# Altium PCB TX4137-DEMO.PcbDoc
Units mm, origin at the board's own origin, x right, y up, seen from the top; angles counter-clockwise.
Board outline 10 x 11 mm, 2 copper layers (Top Layer, Bottom Layer); 11 components, 7 nets, 40 pads, 0 vias.
Unrouted connection lines stored in the file: 3.
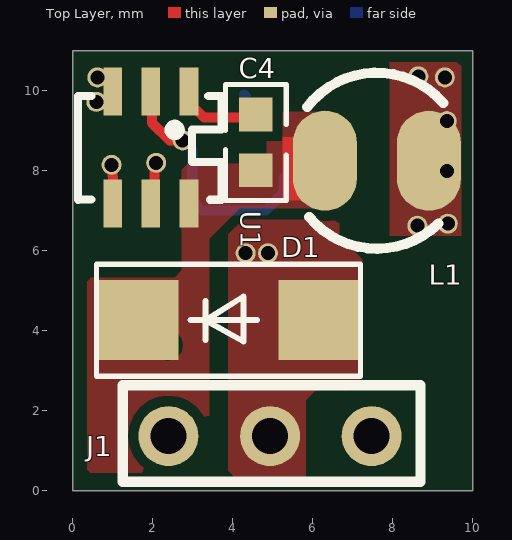
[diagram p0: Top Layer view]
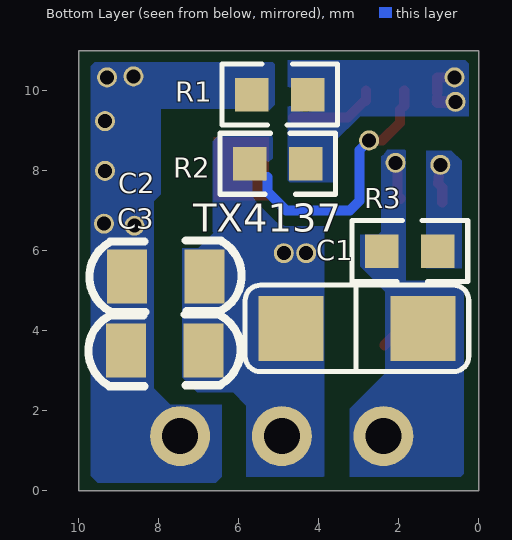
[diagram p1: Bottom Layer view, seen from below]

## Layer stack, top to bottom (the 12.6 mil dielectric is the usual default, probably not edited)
Top Layer: signal copper 0.0356
Dielectric: dielectric 0.32, FR-4, Dk 4.8
Bottom Layer: signal copper 0.0356

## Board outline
0,0 0,11 10,11 10,0

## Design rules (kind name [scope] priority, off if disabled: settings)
Clearance [All] p1: gap=0.254
PlaneConnect [All] p1: planeconnectstyle=Direct reliefexpansion=0.508 reliefentries=4 reliefconductorwidth=0.254 reliefairgap=0.254
PolygonConnect [All] p1: connectstyle=Direct reliefconductorwidth=0.254 reliefentries=4 polygonreliefangle="90 Angle"
RoutingVias [All] p1: holewidth=0.711 width=1.27 viastyle="Through Hole" minholewidth=0.711 minwidth=1.27 maxholewidth=0.711 maxwidth=1.27
SilkscreenOverComponentPads [All] p1: minsilkscreentomaskgap=0.254
SolderMaskExpansion [All] p1: expansion=0.102
TestPointUsage FabricationTestPointUsage [All] p1: valid=0 allowmultiple=FALSE
Testpoint FabricationTestpoint [(IsPad And (OnTopLayer Or OnBottomLayer))] p1: side=3 testpointundercomponent=TRUE minsize=1.016 maxsize=2.54 preferedsize=1.524 minholesize=0 maxholesize=1.016 preferedholesize=0.813 testpointgrid=0.025 style=297 order=0-112345678
Width [All] p1: maxlimit=0.254 minlimit=0.254 preferedwidth=0.254
22 further rules are at their usual default settings.

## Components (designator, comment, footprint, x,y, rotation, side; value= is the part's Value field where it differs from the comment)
C1 "4.7uF/50V" R1206 4.699,4.064 r90 bottom
C2 "10uF/10V" 0805C 7.823,5.359 r90 bottom
C3 "0.1uF/10V" 0805C 7.849,3.505 r90 bottom
C4 "NC" 0603 4.572,8.712 r270 top
D1 "SS26" SMA 3.886,4.267 r0 top
J1 "Component_1" 3PIN_2.54MM 2.388,1.372 r0 top
L1 "22uH" CD43 6.299,8.255 r0 top
R1 "124K" 0603 4.978,9.906 r180 bottom
R2 "40.2K" 0603 5.029,8.179 r0 bottom
R3 "510K" 0603 1.727,5.994 r0 bottom
U1 "TX4137" SOT-23-6 2.9,9.982 r270 top

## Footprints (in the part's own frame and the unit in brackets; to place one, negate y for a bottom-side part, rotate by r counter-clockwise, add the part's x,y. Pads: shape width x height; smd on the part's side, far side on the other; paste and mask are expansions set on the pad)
3PIN_2.54MM [mm]
  round 1.5 hole 0.9: 1(0,0) 2(2.54,0) 3(5.08,0)
  silkscreen extent -1.14,-1.14 6.3,1.27
0603 [mil]
  rect 33x33 smd: 1(-27.5,0) 2(27.5,0)
  silkscreen extent -57,-30 57,30
0805C [mm]
  rect 1.35x1 smd: 1(0,-0.968) 2(0,0.968)
  silkscreen extent -0.89,-1.89 0.9,1.91
CD43 [mm]
  oval 1.6x2.5 smd: 1(0,0) 2(2.6,0)
  silkscreen extent -0.44,-2.2 2.96,2.2
R1206 [mil]
  rect 64x64 smd: 1(0,0) 2(0,-130)
  silkscreen extent -43,-175 42,45
SMA [mm]
  rect 2x2 smd: 1(2.25,0) 2(-2.25,0)
  silkscreen extent -3.3,-1.4 3.3,1.4
SOT-23-6 [mm]
  rect 1.2x0.467 smd: 1(0,0) 2(0,-0.952) 3(0,-1.905) 4(2.794,-1.905) 5(2.794,-0.952) 6(2.794,0)
  silkscreen extent 0.11,-2.77 2.7,0.81

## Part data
C1 C2 C3: library part CAP
C4: library part CAP, "Cap"
D1: library part DI
J1: library part Compo
L1: library part IN

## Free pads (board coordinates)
  round 0.5 hole 0.35: 4(0.584,9.728) 4(0.61,10.338) 4(0.965,8.153) 4(2.083,8.204) 4(2.743,8.763) 4(4.318,5.944) 4(4.877,5.944) 4(8.611,6.629) 4(8.636,10.363) 4(9.296,10.338) 4(9.347,8.001) 4(9.347,9.246) 4(9.373,6.68)

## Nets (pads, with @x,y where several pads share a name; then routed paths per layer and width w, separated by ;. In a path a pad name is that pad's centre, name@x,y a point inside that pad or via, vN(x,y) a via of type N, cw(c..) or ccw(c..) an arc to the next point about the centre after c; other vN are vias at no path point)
GND: C1.1 C2.1 C3.1 D1.1 J1.2 pad.4@2.743,8.763 pad.4@4.318,5.944 pad.4@4.877,5.944 R2.2 U1.2 | length 6.4
  Top Layer w0.254: U1.2@1.867,10.008 1.867,9.627 1.882,9.627 1.974,9.535 1.974,9.206 2.416,8.763 pad.4@2.743,8.763
  Bottom Layer w0.254: pad.4@2.743,8.763 2.984,8.522 2.984,7.252 3.226,7.01 4.817,7.01 5.283,7.476 5.283,7.849
NetC1_2: C1.2 J1.1 pad.4@2.083,8.204 R3.2 U1.5 | length 1.1
  Top Layer w0.254: U1.5@1.956,7.302 2.036,7.382 2.036,8.157 2.083,8.204 pad.4@2.099,8.051
NetC2_2: C2.2 C3.2 J1.3 L1.2 pad.4@8.611,6.629 pad.4@8.636,10.363 pad.4@9.296,10.338 pad.4@9.347,8.001 pad.4@9.347,9.246 pad.4@9.373,6.68 R1.1
NetC4_1: C4.1 U1.1 | length 2.3
  Top Layer w0.254: U1.1@2.819,10.008 2.819,9.982 2.819,9.754 2.839,9.774 3.278,9.335 4.572,9.335 C4.1@4.648,9.335
NetC4_2: C4.2 D1.2 L1.1 U1.6 | length 1.8
  Top Layer w0.254: D1.2@1.382,4.318 1.484,4.42 D1.2@1.535,4.47 ; D1.2@1.585,4.42 1.687,4.318 D1.2@2.362,3.643 ; L1.1@5.766,8.008 5.766,8.255 L1.1@5.766,8.458
NetR1_2: pad.4@0.61,10.338 pad.4@0.584,9.728 R1.2 R2.1 U1.3 | length 1.5
  Top Layer w0.254: pad.4@0.61,10.338 0.995,10.338 1.04,10.338 1.04,9.982 U1.3@1.04,9.957 ; U1.3@1.04,9.728 U1.3@1.04,9.85
  Top Layer w0.3: pad.4@0.584,9.728 0.995,9.728 U1.3@1.04,9.728
  Bottom Layer w0.254: R1.2 R1.2@4.331,9.855
NetR3_1: pad.4@0.965,8.153 R3.1 U1.4 | length 1
  Top Layer w0.254: U1.4@0.914,7.214 0.914,7.58 1.018,7.683 pad.4@0.965,8.153

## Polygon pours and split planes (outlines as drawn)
GND on Top Layer "Top Layer-No Net" (solid, pour order 40): 4.14,6.782 6.655,6.782 6.655,6.375 7.239,5.791 7.239,2.845 6.909,2.515 6.071,2.515 5.817,2.261 5.817,0.356 4.039,0.356 3.886,0.508 3.886,6.528
NetC2_2 on Top Layer "Top Layer-No Net" (solid, pour order 34): 9.601,10.719 9.703,10.617 9.703,6.375 7.925,6.375 7.925,10.719
no net on Top Layer "Top Layer-No Net" (solid, pour order 32): 7.582,6.388
NetC4_2 on Top Layer "Top Layer-No Net" (solid, pour order 18): 0.432,5.334 2.54,5.334 2.718,5.512 2.718,8.026 2.87,8.179 4.851,8.179 4.851,9.119 5.245,9.512 5.283,9.474 6.452,9.474 6.629,9.296 6.629,7.264 6.426,7.061 4.166,7.061 3.404,6.299 3.404,0.66 3.2,0.457 0.432,0.457 0.356,0.533 0.356,5.232 0.432,5.309
no net on Top Layer "Top Layer-No Net" (solid, pour order 14): 3.556,0
NetC2_2 on Bottom Layer "Top Layer-No Net" (solid, pour order 42): 5.105,10.668 5.156,10.719 9.601,10.719 9.703,10.617 9.703,0.381 9.525,0.203 6.579,0.203 6.426,0.356 6.426,2.159 7.722,2.159 8.128,2.565 8.128,7.239 7.95,7.417 7.95,9.55 5.283,9.55 5.245,9.512 5.105,9.652
GND on Bottom Layer "Top Layer-No Net" (solid, pour order 36): 5.182,8.915 6.477,8.915 6.655,8.738 6.655,6.477 6.629,6.452 7.01,6.071 7.417,6.071 7.417,2.845 7.036,2.464 6.147,2.464 5.817,2.134 5.817,0.356 3.886,0.356 3.861,0.33 3.861,6.926 4.174,7.239 5.156,7.239 5.156,8.915 5.207,8.966
no net on Bottom Layer "Top Layer-No Net" (solid, pour order 28): 1.829,6.883
NetC1_2 on Bottom Layer "Top Layer-No Net" (solid, pour order 26): 1.829,8.534 2.337,8.534 2.438,8.433 2.438,6.477 2.515,6.401 2.972,6.401 2.972,5.613 2.337,4.978 2.337,2.946 3.226,2.057 3.226,0.356 0.457,0.356 0.381,0.432 0.381,4.978 0.66,5.258 1.829,5.258
NetR3_1 on Bottom Layer "Top Layer-No Net" (solid, pour order 24): 0.686,8.509 1.321,8.509 1.321,5.563 0.432,5.563 0.432,8.255
no net on Bottom Layer "Top Layer-No Net" (solid, pour order 22): 0.432,7.874
NetR1_2 on Bottom Layer "Top Layer-No Net" (solid, pour order 6): 0.254,10.77 4.775,10.769 4.775,7.772 4.724,7.722 3.632,7.722 3.632,8.712 2.972,9.373 0.254,9.373
no net on Bottom Layer "Top Layer-No Net" (solid, pour order 0): 5.156,11.074

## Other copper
Top Layer:
  rectangle net NetC4_2: 5.245,7.264 6.629,8.847

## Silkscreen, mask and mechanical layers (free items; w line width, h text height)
Bottom Overlay:
  text "TX4137" at 7.137,6.477 h0.7
Mechanical 1:
  lines w0.254: 0,0 10,0 ; 0,0 0,11 ; 0,0 0,11 ; 0,0 10,0 ; 0,11 10,11 ; 0,11 10,11 ; 10,0 10,11 ; 10,0 10,11

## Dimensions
0,11 to 10,11 on Top Overlay
0,0 to 0,11 on Top Overlay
